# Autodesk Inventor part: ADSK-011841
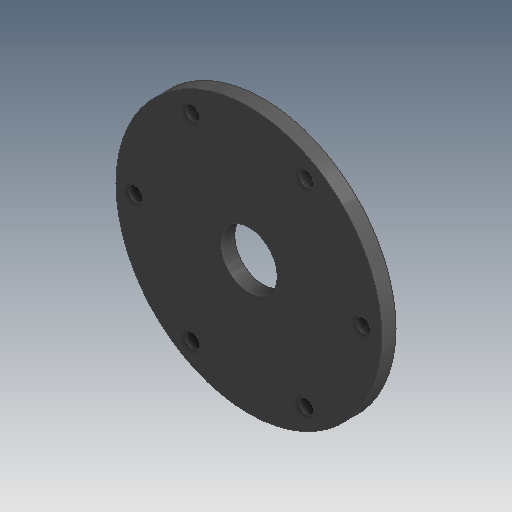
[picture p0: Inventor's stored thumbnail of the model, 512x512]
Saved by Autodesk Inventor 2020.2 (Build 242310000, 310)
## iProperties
Part Number: ADSK-011841
Document SubType Name: Modeling
Material: Générique
Density: 1 g/cm^3
Created: 2017-03
Appearance: Silver
Mass: 221.561 g
Surface Area: 546.927 cm^2
Volume: 221.561 cm^3
Control State: 0
Master: False
Checked Out: False
Length Units: 11272
Angle Units: 11279
Time Units: 11290
Mass Units: 11286
Length Display Precision: 3
Angle Display Precision: 2
Compacted: True
Dimensions: 7x0,4x7 in
Mass: 0,488 lb
VLT_Material: Generic
Revision Number: -
Title: ADSK-011841
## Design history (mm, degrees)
node "Extrusion1" dims "d2" = 9.525, "d3" = 0
node "Extrusion2" dims "d6" = 9.525, "d7" = 0
node "Circular Pattern1" dims "d8" = 60, "d10" = 360 deg
node "Extrusion3" dims "d12" = 9.525, "d13" = 0
node "Solide1"
node "Corps solides"
node "Corps surfaciques"
sketch "Sketch1"
  geometry: L1 (-136.525, -124.46)-(-136.525, -106.998) reference; L2 (0, 152.908)-(0, -145.796) reference; L3 (-159.068, 0)-(156.528, 0) reference; C1 r 88.9 at (0, 0)
  constraints: 2 point on line, 1 centre point
  dimensions: "d1" = 177.8 diameter of C1
sketch "Sketch2"
  geometry: L1 (-106.68, 0)-(142.24, 0) reference; C1 r 88.9 at (0, 0) reference; C2 r 4.763 at (76.2, 0)
  constraints: 1 centre point, 1 point on line
  dimensions: "d4" = 9.525 diameter of C2; "d5" = 76.2 distance of C2.centre C1.centre
sketch "Sketch3"
  geometry: C1 r 88.9 at (0, 0) reference; C2 r 19.05 at (0, 0)
  constraints: 1 centre point, 1 coincident
